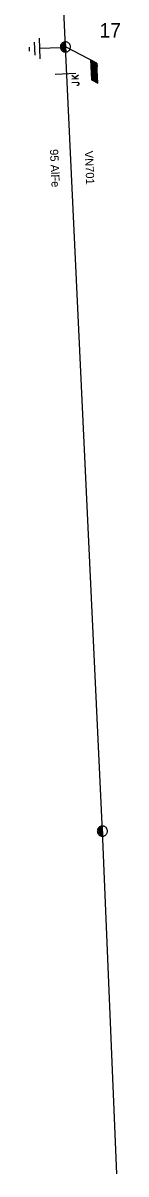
# Model space of a CAD drawing. Extents: x -545588 to -543214, y -1196037 to -1194452.
# Drawn here: x -543609 to -543598, y -1196037.4 to -1195898.4 of the extents above; entities that cross this region are included whole.
import ezdxf

# ---------------------------------------------------------------- set-up
doc = ezdxf.new("R2010")
doc.units = 0
for name, color, linetype in [('DOPLŇ_POPISY', 7, 'Continuous'), ('ELE_EON', 7, 'Continuous'), ('ELE_EON_POPIS', 7, 'Continuous'), ('Implicitní', 7, 'Continuous'), ('POL_ZNAČKA_PRACOVNÍ', 7, 'Continuous'), ('SDEL_EON', 7, 'Continuous'), ('TECH_OCHR_PÁSMO_HRAN', 7, 'Continuous'), ('Vrstva 18', 7, 'Continuous')]:
    doc.layers.add(name, color=color, linetype=linetype)

# ---------------------------------------------------------------- blocks, each defined once
blk = doc.blocks.new('VN840')
at = {"layer": 'POL_ZNAČKA_PRACOVNÍ'}
for points in [[(-0.01, 1.41), (-0.01, -1.09)], [(-1.51, -1.24), (-1.51, -1.15)], [(-1.48, -1.35), (-1.51, -1.24)], [(-1.33, -1.42), (-1.48, -1.35)], [(-1.13, -1.35), (-1.27, -1.42)], [(-1.09, -1.24), (-1.13, -1.35)], [(-1.09, -0.59), (-1.09, -1.24)], [(-0.68, -0.59), (-0.68, -1.42)], [(-0.68, -1.11), (-0.27, -0.59)], [(-0.54, -0.94), (-0.2, -1.42)], [(-1.27, -1.42), (-1.33, -1.42)]]:
    blk.add_lwpolyline(points, dxfattribs=at)
blk = doc.blocks.new('VN440')
at = {"layer": 'ELE_EON_POPIS'}
for points in [[(1.22, 0), (1.21, 0.13), (1.19, 0.25), (1.16, 0.38), (1.11, 0.5), (1.05, 0.61), (0.98, 0.72), (0.9, 0.82), (0.81, 0.91), (0.71, 0.99), (0.6, 1.06), (0.49, 1.12), (0.37, 1.16), (0.25, 1.2), (0.12, 1.22), (-0.01, 1.22), (-0.14, 1.22), (-0.26, 1.2), (-0.39, 1.16), (-0.51, 1.12), (-0.62, 1.06), (-0.73, 0.99), (-0.83, 0.91), (-0.92, 0.82), (-1, 0.72), (-1.07, 0.61), (-1.13, 0.5), (-1.18, 0.38), (-1.21, 0.25), (-1.23, 0.13), (-1.24, 0), (-1.23, -0.13), (-1.21, -0.26), (-1.18, -0.38), (-1.13, -0.5), (-1.07, -0.62), (-1, -0.73), (-0.92, -0.83), (-0.83, -0.92), (-0.73, -1), (-0.62, -1.07), (-0.51, -1.13), (-0.39, -1.17), (-0.26, -1.2), (-0.14, -1.23), (-0.01, -1.23), (0.12, -1.23), (0.25, -1.2), (0.37, -1.17), (0.49, -1.13), (0.6, -1.07), (0.71, -1), (0.81, -0.92), (0.9, -0.83), (0.98, -0.73), (1.05, -0.62), (1.11, -0.5), (1.16, -0.38), (1.19, -0.26), (1.21, -0.13), (1.22, 0)], [(-1.24, 0), (1.22, 0)], [(-1.18, -0.34), (1.1, -0.34)], [(-1.01, -0.63), (0.97, -0.63)], [(-0.74, -0.92), (0.68, -0.92)]]:
    blk.add_lwpolyline(points, dxfattribs=at)
blk = doc.blocks.new('VN810')
at = {"layer": 'POL_ZNAČKA_PRACOVNÍ'}
for points in [[(0, -1.25), (0, -3.75)], [(1.25, -3.75), (-1.25, -3.75)], [(0.77, -4.37), (-0.8, -4.37)], [(0, -5), (-0.25, -5)], [(0.27, -5), (0, -5)]]:
    blk.add_lwpolyline(points, dxfattribs=at)
blk = doc.blocks.new('VN001')
at = {"layer": 'Implicitní'}
for p, q in [((1.73, 3.03), (4.14, 3.03)), ((1.76, 3.08), (4.17, 3.08)), ((1.79, 3.13), (4.2, 3.13)), ((1.82, 3.18), (4.23, 3.18)), ((1.85, 3.23), (4.26, 3.23)), ((1.87, 3.28), (4.29, 3.28)), ((1.9, 3.33), (4.32, 3.33)), ((1.93, 3.38), (4.35, 3.38)), ((1.96, 3.43), (4.37, 3.43)), ((1.99, 3.48), (4.4, 3.48)), ((2.02, 3.53), (4.43, 3.53)), ((2.05, 3.58), (4.46, 3.58)), ((2.07, 3.63), (4.49, 3.63)), ((2.1, 3.68), (4.52, 3.68)), ((2.13, 3.73), (2.54, 3.73))]:
    blk.add_line(p, q, dxfattribs=at)
blk.add_lwpolyline([(2.13, 3.73), (0, 0)], dxfattribs=at)
blk.add_lwpolyline([(4.55, 3.73), (2.13, 3.73), (1.7, 2.98), (4.12, 2.99)], close=True, dxfattribs=at)

msp = doc.modelspace()

# ---------------------------------------------------------------- linework, layer by layer
at = {"layer": 'ELE_EON'}
for points in [[(-543604.63, -1195901.33), (-543605.11, -1195890.68)], [(-543598.42, -1196037.4), (-543600.15, -1195996.01), (-543604.63, -1195901.33)]]:
    msp.add_lwpolyline(points, dxfattribs=at)

# ---------------------------------------------------------------- block references
at = {"layer": 'DOPLŇ_POPISY', "xscale": 0.5000000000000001}
for p, yscale, rotation in [((-543604.63, -1195901.33), 0.4999999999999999, -87.4335499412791), ((-543600.15, -1195996.01), 0.5, -87.29079453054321)]:
    msp.add_blockref('VN440', p, dxfattribs=dict(at, yscale=yscale, rotation=rotation))
at = {"layer": 'POL_ZNAČKA_PRACOVNÍ', "rotation": -87.43419719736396}
msp.add_blockref('VN810', (-543603.99, -1195901.36), dxfattribs=at)
at = {"layer": 'TECH_OCHR_PÁSMO_HRAN', "rotation": -87.43911945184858}
msp.add_blockref('VN001', (-543604.63, -1195901.33), dxfattribs=at)
at = {"layer": 'Vrstva 18', "rotation": 92.70188333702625}
msp.add_blockref('VN840', (-543604.48, -1195904.54), dxfattribs=at)

# ---------------------------------------------------------------- texts
at = {"layer": 'ELE_EON_POPIS'}
msp.add_text('95 AlFe', height=1, rotation=272.709, dxfattribs=at).set_placement((-543606.52, -1195913.69))
at = {"layer": 'POL_ZNAČKA_PRACOVNÍ'}
msp.add_text('17', height=1.75, dxfattribs=at).set_placement((-543600.51, -1195900.2))
at = {"layer": 'SDEL_EON'}
msp.add_text('VN701', height=1, rotation=272.709, dxfattribs=at).set_placement((-543602.3, -1195913.89))

doc.saveas('drawing.dxf')
